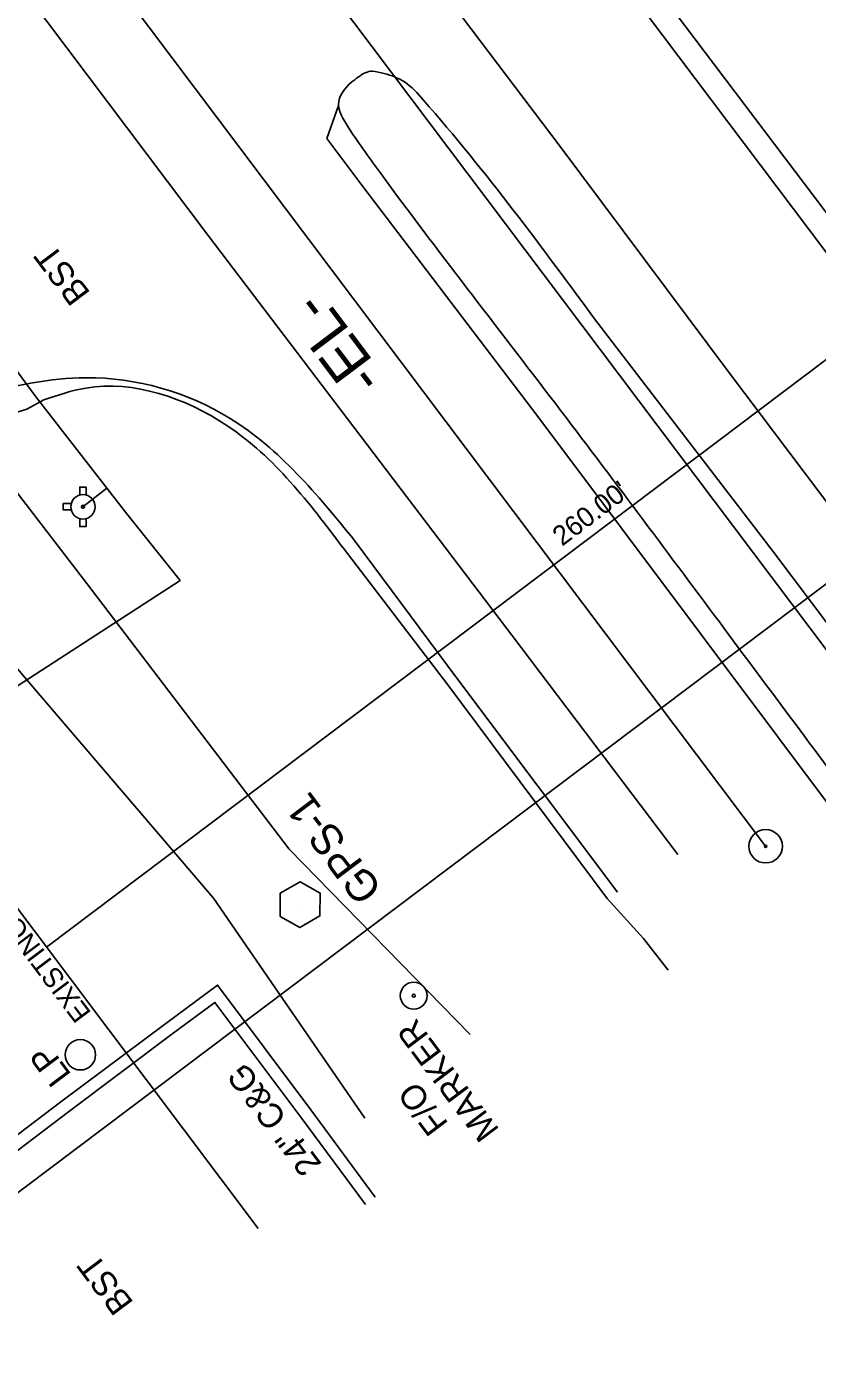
# Model space of a CAD drawing. Extents: x 1262092 to 1264624, y 774970 to 778314.
# Drawn here: x 1264340.5 to 1264468.8, y 775002.7 to 775217.7 of the extents above; entities that cross this region are included whole.
import ezdxf

# ---------------------------------------------------------------- set-up
doc = ezdxf.new("R2010")
doc.units = 0
for name, color, linetype in [('COGO Default Parcel', 7, 'Continuous'), ('CTL Primary Horizontal and Vertical CELL', 7, 'Continuous'), ('Exist Boundary City Limits', 7, 'Continuous'), ('Exist Horizontal Alignment', 7, 'Continuous'), ('Exist Horizontal Alignment Direction Label', 7, 'Continuous'), ('Exist Horizontal Alignment Tick Label', 7, 'Continuous'), ('Exist Right of Way Line', 7, 'Continuous'), ('Exist Right of Way Line Text', 7, 'Continuous'), ('Exist Right of Way Width CELL', 7, 'Continuous'), ('Exist Roads Curbs', 7, 'Continuous'), ('Exist Roads EOP', 7, 'Continuous'), ('Exist Roads EOP Other', 7, 'Continuous'), ('Exist Roads EOT', 7, 'Continuous'), ('Exist Utilities Gas UG Line SUE LOS B', 7, 'Continuous'), ('Exist Utilities Other Located Object Text', 7, 'Continuous'), ('Exist Utilities Other Pole Text', 7, 'Continuous'), ('Exist Utilities Power UG Cable SUE LOS B', 7, 'Continuous'), ('Exist Utilities Telephone UG FO SUE LOS B', 7, 'Continuous'), ('Exist Utilities Water Fire Hydrant CELL', 7, 'Continuous'), ('Exist Utilities Water UG Line SUE LOS B', 7, 'Continuous'), ('Prop Horizontal Alignment', 7, 'Continuous'), ('Prop Lane Lines', 7, 'Continuous'), ('Prop VPI Label', 7, 'Continuous'), ('Sheet Sticker Incomplete CELL', 7, 'Continuous')]:
    doc.layers.add(name, color=color, linetype=linetype)

# ---------------------------------------------------------------- blocks, each defined once
blk = doc.blocks.new('CTL PRIMARY HORIZONTAL AND VERTICAL')
at = {"layer": 'CTL Primary Horizontal and Vertical CELL'}
blk.add_line((0, 0), (0, 0), dxfattribs=at)
blk.add_lwpolyline([(-0.0646, 0.0374), (0.0004, 0.0737), (0.0654, 0.0379), (0.0644, -0.0366), (-0.0006, -0.0743), (-0.0646, -0.0381)], close=True, dxfattribs=at)
blk = doc.blocks.new('EXIST UTILITIES WATER FIRE HYDRANT')
at = {"layer": 'Exist Utilities Water Fire Hydrant CELL'}
blk.add_line((0, 0), (0, 0), dxfattribs=at)
for points in [[(-0.01025, 0.03825), (-0.01025, 0.064), (0.01025, 0.064), (0.01025, 0.03775)], [(-0.03825, 0.01025), (-0.064, 0.01025), (-0.064, -0.01025), (-0.03825, -0.01025)], [(-0.01025, -0.03825), (-0.01025, -0.064), (0.01025, -0.064), (0.01025, -0.03775)]]:
    blk.add_lwpolyline(points, dxfattribs=at)
for radius in [0.03954, 0.00485]:
    blk.add_circle((0, 0), radius, dxfattribs=at)

msp = doc.modelspace()

# ---------------------------------------------------------------- linework, layer by layer
at = {"layer": 'COGO Default Parcel'}
msp.add_line((1264624.2, 775243.33), (1264304.64, 775002.74), dxfattribs=at)
at = {"layer": 'Exist Boundary City Limits'}
msp.add_line((1264481.92, 775101.04), (1263870.58, 775912.68), dxfattribs=at)
at = {"layer": 'Exist Horizontal Alignment'}
msp.add_line((1264460.35, 775084.79), (1262255.05, 778012.66), dxfattribs=at)
at = {"layer": 'Exist Horizontal Alignment Tick Label'}
for radius in [2.71, 0.187]:
    msp.add_circle((1264460.35, 775084.79), radius, dxfattribs=at)
at = {"layer": 'Exist Right of Way Line'}
msp.add_line((1263350.65, 776386.89), (1264378.08, 775022.83), dxfattribs=at)
at = {"layer": 'Exist Right of Way Width CELL'}
for p in [(1264551.4, 775224.86), (1264343.72, 775068.44)]:
    msp.add_line(p, (1264435.17, 775137.32), dxfattribs=at)
at = {"layer": 'Exist Roads Curbs'}
msp.add_lwpolyline([(1264300.15, 775008.68), (1264301.96, 775010.02), (1264313.91, 775018.98), (1264318.12, 775022.19), (1264333.63, 775033.94), (1264346.06, 775043.34), (1264363.09, 775056.09), (1264371.46, 775062.28), (1264386.59, 775042.09), (1264397.05, 775027.94)], dxfattribs=at)
at = {"layer": 'Exist Roads EOP'}
msp.add_line((1264343.27, 775157.13), (1264340.53, 775155.63), dxfattribs=at)
for points in [[(1264356.79, 775338.17), (1264383.65, 775302.46), (1264413.48, 775262.67), (1264443.98, 775222.14), (1264473.2, 775183.54), (1264503.06, 775144), (1264525.38, 775114.25)], [(1264356.79, 775338.17), (1264383.65, 775302.46), (1264413.48, 775262.67), (1264443.98, 775222.14), (1264473.2, 775183.54)], [(1264433.14, 775169.57), (1264461.51, 775132.64), (1264489.74, 775095.18)], [(1264434.66, 775076.31), (1264408.8, 775110.93), (1264391.84, 775133.14)], [(1264444.56, 775064.7), (1264440.52, 775069.83), (1264434.66, 775076.31)]]:
    msp.add_lwpolyline(points, dxfattribs=at)
for points in [[(1264477.42, 775088.17), (1264452.84, 775121.14), (1264426.3, 775156.48), (1264397.98, 775193.76), (1264392.76, 775201.19), (1264391.11, 775205.53), (1264393.71, 775209.04), (1264394.88, 775209.86), (1264396.01, 775210.36), (1264396.53, 775210.44)], [(1264396.53, 775210.44), (1264398.5, 775210.04), (1264401.77, 775208.67), (1264404.83, 775205.76), (1264433.14, 775169.57)], [(1264391.84, 775133.14), (1264372.97, 775153), (1264350.13, 775159.06), (1264343.27, 775157.13)]]:
    msp.add_spline(points, degree=3, dxfattribs=at)
at = {"layer": 'Exist Roads EOP Other'}
for points in [[(1264340.53, 775155.63), (1264338.09, 775154.89), (1264334.86, 775154.31), (1264332.74, 775154.08), (1264330.26, 775154.66), (1264327.44, 775155.61), (1264326.53, 775156.81)], [(1264301.4, 775007.11), (1264303.16, 775008.41), (1264315.12, 775017.38), (1264319.33, 775020.59), (1264334.84, 775032.34), (1264347.27, 775041.74), (1264364.29, 775054.47), (1264371.05, 775059.47), (1264384.98, 775040.89), (1264395.46, 775026.71)]]:
    msp.add_lwpolyline(points, dxfattribs=at)
at = {"layer": 'Exist Roads EOT'}
for points in [[(1264446.09, 775083.45), (1264419.18, 775119.01), (1264392.54, 775154.06), (1264369.93, 775183.78), (1264343.71, 775218.57), (1264317, 775253.46), (1264292.67, 775285.65), (1264265.72, 775321.45), (1264237.79, 775358.61), (1264211.14, 775394.4), (1264184.66, 775429.54), (1264159.42, 775463.25), (1264133.92, 775497.47), (1264108.52, 775531.19), (1264082.14, 775566.55), (1264057.31, 775599.4), (1264024.24, 775643.38), (1263996.61, 775679.88), (1263968.79, 775716.67), (1263941.99, 775752.17)], [(1264353.93, 775336.04), (1264380.37, 775300.68), (1264410.53, 775260.48), (1264440.99, 775219.76), (1264470.13, 775181.13), (1264500.1, 775142.08), (1264522.23, 775111.94)], [(1264368.24, 775276.07), (1264395.5, 775239.87), (1264426.84, 775198.42), (1264454.48, 775161.48), (1264481.03, 775126.28), (1264498.94, 775102.43)], [(1264389.21, 775199.49), (1264391.1, 775204.86)], [(1264474.61, 775086.14), (1264449.87, 775119.12), (1264423.43, 775154.47), (1264395, 775191.73), (1264389.21, 775199.49)], [(1264436.31, 775077.34), (1264410.29, 775112.02), (1264393.68, 775134.37)]]:
    msp.add_lwpolyline(points, dxfattribs=at)
msp.add_spline([(1264393.68, 775134.37), (1264373.52, 775154.13), (1264350.12, 775160.74), (1264341.47, 775159.89), (1264336.92, 775159)], degree=3, dxfattribs=at)
at = {"layer": 'Exist Utilities Gas UG Line SUE LOS B'}
msp.add_circle((1264349.22, 775050.99), 2.46, dxfattribs=at)
at = {"layer": 'Exist Utilities Power UG Cable SUE LOS B'}
msp.add_lwpolyline([(1264395.36, 775040.74), (1264370.8, 775076.36), (1264340.19, 775112.15), (1264308.39, 775149.99), (1264277.8, 775188.45), (1264254.82, 775218.46), (1264230.51, 775255.61), (1264208, 775290.17), (1264185.34, 775318.09), (1264158.04, 775354.59), (1264133.61, 775386.92), (1264107.25, 775423.32), (1264089.56, 775447.66), (1264061.08, 775477.65), (1264037.85, 775505.73), (1264032.45, 775511.96), (1264026.57, 775514.09), (1263970.61, 775511.19)], dxfattribs=at)
at = {"layer": 'Exist Utilities Telephone UG FO SUE LOS B'}
msp.add_lwpolyline([(1264412.43, 775054.27), (1264383.09, 775084.33), (1264350.27, 775127.37), (1264319.47, 775167.42), (1264288.52, 775206.2), (1264253.33, 775248.38), (1264233.02, 775276.08), (1264197.49, 775318.53), (1264165.2, 775359.15), (1264131.6, 775400.04), (1264102.3, 775438.18), (1264079.45, 775463.73), (1264046.01, 775506.17), (1264034.16, 775523.07), (1264026.26, 775546.1), (1264015.26, 775566.11), (1263989.3, 775607.52), (1263955.25, 775658.94), (1263921.26, 775710.27), (1263888.91, 775754.45), (1263860.31, 775793.96), (1263832.43, 775832.72), (1263818.26, 775866.25), (1263816.28, 775877)], dxfattribs=at)
at = {"layer": 'Exist Utilities Water UG Line SUE LOS B'}
msp.add_line((1264353.54, 775142.84), (1264349.64, 775139.81), dxfattribs=at)
msp.add_lwpolyline([(1264262.47, 775052.4), (1264270.03, 775057.49), (1264308.25, 775083.86), (1264311.99, 775091.01), (1264333.07, 775106.94), (1264365.39, 775127.89), (1264356.78, 775138.68), (1264342.07, 775157.58), (1264315.02, 775194.18), (1264289.27, 775228.94), (1264261.35, 775265.49), (1264234.66, 775298.88), (1264204.95, 775340.41), (1264179.39, 775376.51), (1264153.98, 775411.4), (1264121.66, 775450.17), (1264092.98, 775486.7), (1264069.57, 775517.58), (1264043.23, 775551.19), (1264018.68, 775582.59), (1263995.06, 775614.62), (1263975.68, 775643.74), (1263951.8, 775677.27), (1263925.33, 775714.09)], dxfattribs=at)
at = {"layer": 'Prop Lane Lines'}
for radius in [2.18, 0.24]:
    msp.add_circle((1264403.28, 775060.57), radius, dxfattribs=at)

# ---------------------------------------------------------------- block references
at = {"layer": 'CTL Primary Horizontal and Vertical CELL', "xscale": 50, "yscale": 50}
msp.add_blockref('CTL PRIMARY HORIZONTAL AND VERTICAL', (1264384.85, 775075.32), dxfattribs=at)
msp.add_blockref('CTL PRIMARY HORIZONTAL AND VERTICAL', (1264384.85, 775075.32), dxfattribs=at)
at = {"layer": 'Exist Utilities Water Fire Hydrant CELL', "xscale": 50, "yscale": 50}
msp.add_blockref('EXIST UTILITIES WATER FIRE HYDRANT', (1264349.64, 775139.81), dxfattribs=at)

# ---------------------------------------------------------------- texts
at = {"layer": 'Exist Horizontal Alignment Direction Label'}
msp.add_text('-EL-', height=7, rotation=126.9874, dxfattribs=at).set_placement((1264398.7, 775160.89))
at = {"layer": 'Exist Right of Way Line Text'}
msp.add_text('EXISTING R/W', height=3.2, rotation=126.9874, dxfattribs=at).set_placement((1264351.08, 775057.78))
at = {"layer": 'Exist Right of Way Width CELL'}
msp.add_text("260.00'", height=3.2, rotation=36.9874, dxfattribs=at).set_placement((1264427.33, 775133.32))
at = {"layer": 'Exist Utilities Other Located Object Text'}
for s, p in [('MARKER', (1264417.28, 775038.84)), ('F/O', (1264409.02, 775039.83))]:
    msp.add_text(s, height=4, rotation=126.9746, dxfattribs=at).set_placement(p)
at = {"layer": 'Exist Utilities Other Pole Text'}
msp.add_text('LP', height=4, rotation=126.9746, dxfattribs=at).set_placement((1264347.87, 775047.78))
at = {"layer": 'Prop Horizontal Alignment'}
for p in [(1264350.96, 775174.44), (1264350.96, 775174.44), (1264357.96, 775010.79)]:
    msp.add_text('BST', height=4, rotation=126.9874, dxfattribs=at).set_placement(p)
at = {"layer": 'Prop VPI Label'}
msp.add_text('GPS-1', height=5, rotation=126.9874, dxfattribs=at).set_placement((1264398.36, 775077.85))
at = {"layer": 'Sheet Sticker Incomplete CELL'}
msp.add_text('24" C&G', height=4, rotation=126.9746, dxfattribs=at).set_placement((1264388.47, 775033.27))

doc.saveas('drawing.dxf')
